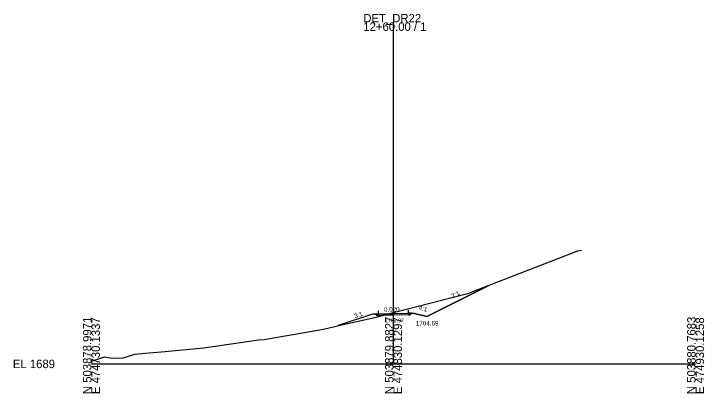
# Model space of a CAD drawing. Extents: x -26 to 1203, y -10 to 9633.
# Drawn here: x -25.7 to 202.8, y 6490.3 to 6615.8 of the extents above; entities that cross this region are included whole.
import ezdxf

# ---------------------------------------------------------------- set-up
doc = ezdxf.new("R2010")
doc.units = 0
for name, color, linetype in [('Exist Cross Section Cell', 7, 'Continuous'), ('Exist XS Center Line Elevation Label', 7, 'Continuous'), ('Exist XS Ground Line', 7, 'Continuous'), ('Prop XS Ditch Slope Text', 7, 'Continuous'), ('Prop XS Ditch Standard Text', 7, 'Continuous'), ('Prop XS Earthwork Shape', 7, 'Continuous'), ('Prop XS EOT Tick Mark', 7, 'Continuous'), ('Prop XS Finish Grade', 7, 'Continuous'), ('Prop XS Finish Grade Earthwork', 7, 'Continuous'), ('Prop XS Finish Grade Pavement', 7, 'Continuous'), ('Prop XS Pvmt Edge Slope', 7, 'Continuous'), ('Prop XS SE Text', 7, 'Continuous'), ('Prop XS Shoulder Borrow Shape', 7, 'Continuous'), ('Prop XS Side Slope Text', 7, 'Continuous'), ('Prop XS Subgrade Earthwork', 7, 'Continuous')]:
    doc.layers.add(name, color=color, linetype=linetype)

msp = doc.modelspace()

# ---------------------------------------------------------------- linework, layer by layer
at = {"layer": 'Exist Cross Section Cell'}
for p, q in [((100, 6500), (100, 6612.95)), ((0, 6500), (100, 6500)), ((100, 6500), (200, 6500))]:
    msp.add_line(p, q, dxfattribs=at)
at = {"layer": 'Exist XS Ground Line'}
msp.add_lwpolyline([(0, 6500.9), (4.37, 6502.34), (6.85, 6501.86), (10.5, 6502.04), (14.37, 6503.25), (17.8, 6503.56), (24.37, 6504.09), (37.1, 6505.27), (48.57, 6506.93), (55.36, 6507.95), (57.13, 6508.09), (76.79, 6511.53), (82.85, 6512.9), (94.27, 6515.5), (100, 6516.97), (124.1, 6523.16), (124.57, 6523.33), (126.29, 6523.93), (161, 6537.34), (162.25, 6537.65)], dxfattribs=at)
at = {"layer": 'Prop XS Earthwork Shape'}
for points in [[(126.29, 6523.93), (131.55, 6525.96), (111, 6515.69), (107, 6516.69), (106.02, 6516.73), (105.53, 6516.24), (105, 6516.23), (100, 6516.13), (96.44, 6516.06), (100, 6516.97), (124.1, 6523.16), (124.57, 6523.33)], [(93.98, 6516.49), (93, 6516.41), (81.7, 6512.64), (82.85, 6512.9), (94.27, 6515.5), (96.44, 6516.06), (95, 6516.03), (94.45, 6516.02)]]:
    msp.add_lwpolyline(points, close=True, dxfattribs=at)
at = {"layer": 'Prop XS EOT Tick Mark'}
for p, q in [((105, 6516.77), (105, 6517.77)), ((95, 6516.57), (95, 6517.57))]:
    msp.add_line(p, q, dxfattribs=at)
at = {"layer": 'Prop XS Finish Grade'}
for p, q in [((95, 6516.57), (93.98, 6516.49)), ((105, 6516.77), (106.02, 6516.73))]:
    msp.add_line(p, q, dxfattribs=at)
at = {"layer": 'Prop XS Finish Grade Earthwork'}
for p, q in [((111, 6515.69), (131.55, 6525.96)), ((93, 6516.41), (81.7, 6512.64)), ((93.98, 6516.49), (93, 6516.41)), ((106.02, 6516.73), (107, 6516.69)), ((107, 6516.69), (111, 6515.69))]:
    msp.add_line(p, q, dxfattribs=at)
at = {"layer": 'Prop XS Finish Grade Pavement'}
for p, q in [((95, 6516.57), (100, 6516.67)), ((100, 6516.67), (105, 6516.77))]:
    msp.add_line(p, q, dxfattribs=at)
at = {"layer": 'Prop XS Pvmt Edge Slope'}
for p, q in [((95, 6516.57), (94.45, 6516.02)), ((105, 6516.77), (105.53, 6516.24))]:
    msp.add_line(p, q, dxfattribs=at)
at = {"layer": 'Prop XS Shoulder Borrow Shape'}
for points in [[(95, 6516.57), (94.45, 6516.02), (93.98, 6516.49)], [(105.53, 6516.24), (106.02, 6516.73), (105, 6516.77)]]:
    msp.add_lwpolyline(points, close=True, dxfattribs=at)
at = {"layer": 'Prop XS Subgrade Earthwork'}
for p, q in [((94.45, 6516.02), (93.98, 6516.49)), ((95, 6516.03), (94.45, 6516.02)), ((100, 6516.13), (95, 6516.03)), ((105, 6516.23), (100, 6516.13)), ((105, 6516.23), (105.53, 6516.24)), ((105.53, 6516.24), (106.02, 6516.73))]:
    msp.add_line(p, q, dxfattribs=at)

# ---------------------------------------------------------------- texts
at = {"layer": 'Exist Cross Section Cell'}
for s, p in [('DET_DR22', (90, 6612.95)), ('12+60.00 / 1', (90, 6610.15)), ('EL 1689', (-26, 6498.6))]:
    msp.add_text(s, height=2.8, dxfattribs=at).set_placement(p)
for s, p in [('N 503878.9971', (0, 6490)), ('E 474730.1337', (2.8, 6490)), ('N 503879.8827', (100, 6490)), ('E 474830.1297', (102.8, 6490)), ('N 503880.7683', (200, 6490)), ('E 474930.1258', (202.8, 6490))]:
    msp.add_text(s, height=2.8, rotation=90, dxfattribs=at).set_placement(p)
at = {"layer": 'Exist XS Center Line Elevation Label'}
msp.add_text('1705.97', height=1.25, dxfattribs=at).set_placement((97.16, 6513.72))
at = {"layer": 'Prop XS Ditch Slope Text'}
msp.add_text('4:1', height=1.5, rotation=345.9638, dxfattribs=at).set_placement((108.21, 6517.93))
at = {"layer": 'Prop XS Ditch Standard Text'}
msp.add_text('1704.69', height=1.5, dxfattribs=at).set_placement((107.39, 6512.69))
at = {"layer": 'Prop XS SE Text'}
msp.add_text('0.020', height=1.5, rotation=1.1458, dxfattribs=at).set_placement((96.85, 6517.23))
at = {"layer": 'Prop XS Side Slope Text'}
for s, rotation, p in [('2:1', 26.5651, (119.54, 6521.63)), ('3:1', 18.4349, (87.23, 6515.04))]:
    msp.add_text(s, height=1.5, rotation=rotation, dxfattribs=at).set_placement(p)

doc.saveas('drawing.dxf')
